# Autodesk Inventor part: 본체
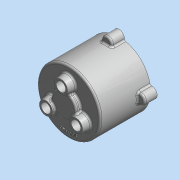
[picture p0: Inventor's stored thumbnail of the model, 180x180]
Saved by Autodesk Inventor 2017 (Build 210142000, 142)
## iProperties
Created: 2021-07
Part Number: 본체
Document SubType Name: 모델링
Designer: mdu
Material: 알루미늄 6061
Density: 2.71 g/cm^3
Appearance: 알루미늄 - 평지
Mass: 473.477 g
Surface Area: 688.944 cm^2
Volume: 174.715 cm^3
변환 표준: STEP AP214IS
파일 이름: C:\Users\SeoGD\Desktop\?쒗뿕\紐몄껜.stp
전처리기: Build: 253, Release: 2010 SP1 - Date: Wed 07/29/2009
전송 단위: 밀리미터
불확실성: 0.01
Author: mdu
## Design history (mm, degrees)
sketch "스케치2"
  geometry: C1 r 50 at (0, 0); 1 further point
  constraints: 1 centre point, 1 coincident
  dimensions: "d9" = 100 diameter of C1
extrude "돌출2" new body sketch "스케치2" distance "d10" = 80; taper "d11" = 0 deg
feature "쉘1" dims "d12" = 5
sketch "스케치3" dims "d13" = 55
  geometry: C1 r 7.5 at (0, 27.5); C2 r 12.5 at (0, 27.5); 2 further points
  constraints: 2 centre point, 2 coincident, 2 vertical alignment, 2 other
  dimensions: "d14" = 15 diameter of C1; "d15" = 25 diameter of C2
extrude "돌출3" join sketch "스케치3" distance "d16" = 12; taper "d17" = -10 deg
sketch "스케치4"
  geometry: L1 (0, 0)-(0, 88); L2 (0, 70)-(14, 70); L3 (-45, 75)-(45, 75) reference; L4 (-50, 80)-(50, 80) reference; L5 (14, 70)-(14, 75); L6 (20, 80)-(20, 88); L7 (20, 88)-(0, 88); L8 (20, 80)-(14, 75)
  constraints: 12 end point, 3 point on line, 2 perpendicular, 1 vertical
  dimensions: "d34" = 40 diameter of L6 L1; "d35" = 90 deg angle of L5 L3; "d36" = 5 distance between parallel lines of L2 L3; "d37" = 8 distance between parallel lines of L7 L4; "d51" = 28 diameter of L5.end L1
revolve "회전1" sketch "스케치4" stored, may be unused: angle "d38" = 90 deg
hole "구멍3" diameter "d41" = 15; stored, may be unused: countersink angle "d45" = 90 deg, drill point angle "d47" = 0 deg; dims "d39" = 10, "d40" = 10, "d42" = 6, "d43" = 22, "d44" = 13, "d46" = 15
chamfer "모따기2" distance "d48" = 1; stored, may be unused: second distance "d49" = 2, angle "d50" = 45 deg
fillet "모깎기4" dims "d78" = 3
hole "구멍2" diameter "d20" = 15; stored, may be unused: countersink angle "d24" = 90 deg, drill point angle "d26" = 118 deg; dims "d21" = 6, "d22" = 25, "d23" = 1, "d25" = 15, "d76" = 10, "d77" = 10
chamfer "모따기1" distance "d27" = 1; stored, may be unused: second distance "d28" = 2, angle "d29" = 45 deg
sketch "스케치9"
  geometry: C1 r 12.5 at (0, 0) reference; C2 r 12.5 at (-23.816, -41.25) reference; C3 r 12.5 at (23.816, -41.25) reference; 1 further point
extrude "돌출5" cut sketch "스케치9" stored distance "d79" = 10; taper "d80" = 0 deg
fillet "모깎기1" dims "d52" = 3
fillet "모깎기2" dims "d53" = 3, "d72" = 0.2
sketch "스케치5"
  geometry: A1 r 50 centre (0, 0) between (50, 0) and (-8.074, 49.344) reference; A2 r 8.5 centre (0, 52) between (8.074, 49.344) and (-8.074, 49.344); 1 further point
  constraints: 5 point on circle, 1 centre point, 1 horizontal alignment
  dimensions: "d54" = 90 deg dimension on point (0, 0) A2.centre A1.start; "d55" = 52 distance of A2.centre point (0, 0); "d56" = 17 diameter of A2
extrude "돌출4" join sketch "스케치5" distance "d57" = 20; taper "d58" = 0 deg
fillet "모깎기3" dims "d59" = 3
hole "구멍4" diameter "d62" = 4.134; stored, may be unused: countersink angle "d66" = 90 deg, drill point angle "d68" = 118 deg; dims "d60" = 10, "d61" = 10, "d63" = 12, "d64" = 22, "d65" = 13, "d67" = 15
sketch "스케치6"
  geometry: C1 r 47 at (0, 0) reference; C2 r 42.5 at (0, 0); 1 further point
  constraints: 1 centre point, 1 coincident, 1 other
  dimensions: "d73" = 85 diameter of C2
feature "엠보싱1" sketch "스케치6" dims "d34" = 40, "d35" = 90 deg, "d36" = 5, "d37" = 8, "d51" = 28, "d74" = 1, "d75" = 0
node "솔리드1"
node "솔리드 본체"
node "곡면 본체"
pattern_circular "원형 패턴1" dims angle "d31" = 360 deg
pattern_circular "원형 패턴2" dims angle "d70" = 360 deg
node "솔리드2"
